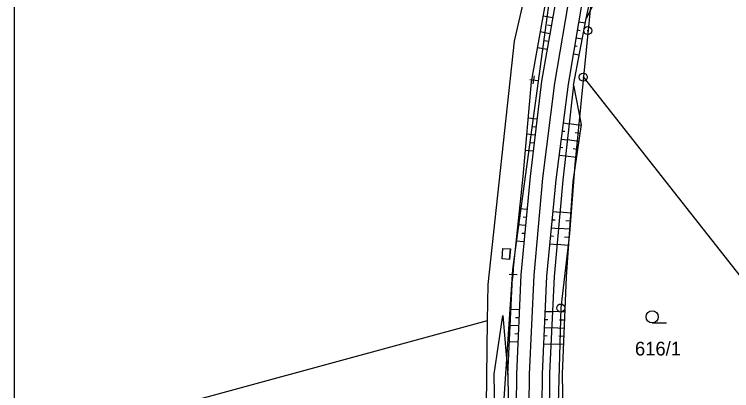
# Model space of a CAD drawing. Extents: x -558358 to -557517, y -1073786 to -1073189.
# Drawn here: x -558357.5 to -558268.9, y -1073715.2 to -1073668.8 of the extents above; entities that cross this region are included whole.
import ezdxf

# ---------------------------------------------------------------- set-up
doc = ezdxf.new("R2010")
doc.units = 0
for name, color, linetype in [('Body', 7, 'Continuous'), ('Hranice parcel', 7, 'Continuous'), ('Kolej', 7, 'Continuous'), ('Lomové body_krizky', 7, 'Continuous'), ('Návěst místo trati', 7, 'Continuous'), ('Parcelní čísla', 7, 'Continuous'), ('Přejezd - štěrkové lože', 7, 'Continuous'), ('Sonda - šrafa - vrstevnice', 7, 'Continuous'), ('Svazek obcí údolí Desné', 7, 'Continuous'), ('Vrstva 1', 7, 'Continuous'), ('Značky kultur', 7, 'Continuous'), ('ŽKN drážní hranice', 7, 'Continuous')]:
    doc.layers.add(name, color=color, linetype=linetype)

msp = doc.modelspace()

# ---------------------------------------------------------------- linework, layer by layer
at = {"layer": 'Body'}
for p, q in [((-558297.201, -1073697.684), (-558296.265, -1073697.749)), ((-558296.373, -1073699.041), (-558297.304, -1073698.971))]:
    msp.add_line(p, q, dxfattribs=at)
for points in [[(-558296.265, -1073697.749), (-558296.373, -1073699.041), (-558297.304, -1073698.971), (-558297.201, -1073697.684), (-558296.265, -1073697.749)], [(-558297.304, -1073698.971), (-558297.304, -1073698.971), (-558297.201, -1073697.684), (-558297.201, -1073697.684)], [(-558296.373, -1073699.041), (-558296.373, -1073699.041), (-558296.265, -1073697.749), (-558296.265, -1073697.749)]]:
    msp.add_lwpolyline(points, dxfattribs=at)
at = {"layer": 'Hranice parcel'}
for p, q in [((-558261.12, -1073709.7), (-558287.25, -1073676.53)), ((-558339.57, -1073717.56), (-558299.09, -1073706.57))]:
    msp.add_line(p, q, dxfattribs=at)
at = {"layer": 'Kolej'}
msp.add_lwpolyline([(-558287.365, -1073784.156), (-558289.56, -1073772.871), (-558290.655, -1073766.206), (-558291.244, -1073762.209), (-558292.77, -1073749.061), (-558293.618, -1073737.469), (-558294.023, -1073725.055), (-558293.93, -1073713.176), (-558293.343, -1073701.022), (-558292.273, -1073689.007), (-558290.767, -1073677.306), (-558288.802, -1073665.65), (-558286.315, -1073653.735), (-558283.342, -1073641.942), (-558279.999, -1073630.567), (-558276.235, -1073619.431), (-558271.867, -1073608.038), (-558267.229, -1073597.243), (-558261.985, -1073586.238), (-558256.491, -1073575.8), (-558250.409, -1073565.278), (-558246.055, -1073558.303)], dxfattribs=at)
at = {"layer": 'Lomové body_krizky'}
for points in [[(-558281.763, -1073647.437), (-558282.833, -1073654.479), (-558285.332, -1073666.203), (-558286.935, -1073669.338)], [(-558286.935, -1073669.338), (-558286.218, -1073666.1), (-558283.779, -1073654.254), (-558281.763, -1073647.437)], [(-558288.463, -1073677.538), (-558289.796, -1073689.277), (-558290.88, -1073701.164), (-558291.444, -1073713.13), (-558291.51, -1073724.978), (-558290.98, -1073737.221), (-558290.303, -1073748.774), (-558289.412, -1073757.852), (-558288.852, -1073759.4), (-558286.909, -1073759.37), (-558284.741, -1073757.826)], [(-558288.463, -1073677.538), (-558287.551, -1073682.415), (-558288.544, -1073689.423), (-558289.374, -1073701.199), (-558289.889, -1073713.191), (-558289.693, -1073724.945), (-558289.132, -1073737.15), (-558288.385, -1073748.554), (-558287.031, -1073757.61), (-558284.468, -1073754.179), (-558281.215, -1073749.294)], [(-558293.853, -1073762.99), (-558295.99, -1073758.489), (-558297.205, -1073749.273), (-558297.706, -1073737.714), (-558298.061, -1073725.185), (-558298.29, -1073713.182), (-558297.21, -1073705.961)], [(-558297.21, -1073705.961), (-558296.594, -1073713.219), (-558296.433, -1073725.029), (-558296.684, -1073737.611), (-558295.948, -1073749.108), (-558294.01, -1073759.601), (-558293.853, -1073762.99)]]:
    msp.add_lwpolyline(points, dxfattribs=at)
at = {"layer": 'Návěst místo trati'}
for p, q in [((-558293.863, -1073676.832), (-558292.873, -1073676.978)), ((-558293.441, -1073677.4), (-558293.295, -1073676.41)), ((-558296.441, -1073700.841), (-558295.443, -1073700.909)), ((-558295.976, -1073701.374), (-558295.908, -1073700.376))]:
    msp.add_line(p, q, dxfattribs=at)
at = {"layer": 'Přejezd - štěrkové lože'}
for p, q in [((-558291.044, -1073669.227), (-558292.223, -1073669.017)), ((-558288.463, -1073677.538), (-558286.935, -1073669.338)), ((-558287.812, -1073669.746), (-558287.036, -1073669.878)), ((-558291.22, -1073670.212), (-558291.691, -1073670.127)), ((-558287.978, -1073670.733), (-558287.675, -1073670.784)), ((-558291.396, -1073671.196), (-558292.575, -1073670.986)), ((-558291.571, -1073672.181), (-558292.043, -1073672.096)), ((-558288.145, -1073671.719), (-558287.402, -1073671.844)), ((-558291.747, -1073673.165), (-558292.926, -1073672.954)), ((-558288.312, -1073672.704), (-558288.021, -1073672.754)), ((-558288.479, -1073673.69), (-558287.768, -1073673.811)), ((-558292.999, -1073681.733), (-558294.065, -1073681.607)), ((-558289.723, -1073682.209), (-558289.004, -1073682.301)), ((-558293.117, -1073682.727), (-558293.531, -1073682.677)), ((-558293.235, -1073683.72), (-558294.24, -1073683.6)), ((-558289.85, -1073683.201), (-558289.557, -1073683.239)), ((-558293.353, -1073684.713), (-558293.742, -1073684.666)), ((-558289.977, -1073684.193), (-558289.23, -1073684.289)), ((-558293.471, -1073685.705), (-558294.414, -1073685.593)), ((-558290.104, -1073685.185), (-558289.8, -1073685.224)), ((-558290.231, -1073686.177), (-558289.455, -1073686.276)), ((-558294.222, -1073692.875), (-558295.121, -1073692.791)), ((-558290.997, -1073693.143), (-558290.156, -1073693.223)), ((-558294.315, -1073693.87), (-558294.68, -1073693.836)), ((-558291.093, -1073694.139), (-558290.754, -1073694.171)), ((-558294.409, -1073694.866), (-558295.334, -1073694.779)), ((-558291.188, -1073695.134), (-558290.338, -1073695.215)), ((-558294.502, -1073695.862), (-558294.877, -1073695.827)), ((-558291.284, -1073696.129), (-558290.942, -1073696.162)), ((-558294.595, -1073696.857), (-558295.547, -1073696.768)), ((-558291.38, -1073697.124), (-558290.519, -1073697.207)), ((-558295.161, -1073705.247), (-558296.215, -1073705.202)), ((-558291.951, -1073705.444), (-558291.084, -1073705.482)), ((-558295.204, -1073706.246), (-558295.627, -1073706.228)), ((-558291.995, -1073706.443), (-558291.649, -1073706.459)), ((-558295.247, -1073707.246), (-558296.31, -1073707.2)), ((-558292.038, -1073707.442), (-558291.178, -1073707.48)), ((-558295.29, -1073708.245), (-558295.717, -1073708.227)), ((-558292.082, -1073708.441), (-558291.739, -1073708.456)), ((-558295.332, -1073709.244), (-558296.404, -1073709.198)), ((-558292.125, -1073709.44), (-558291.272, -1073709.478))]:
    msp.add_line(p, q, dxfattribs=at)
for points in [[(-558236.565, -1073541.181), (-558242.627, -1073550.035), (-558251.802, -1073564.356), (-558258.077, -1073574.962), (-558263.679, -1073585.424), (-558268.893, -1073596.634), (-558273.555, -1073607.365), (-558277.841, -1073618.92), (-558281.554, -1073630.049), (-558284.863, -1073641.542), (-558287.933, -1073653.35), (-558290.359, -1073665.391), (-558292.442, -1073677.056), (-558293.843, -1073688.831), (-558294.976, -1073700.921), (-558295.502, -1073713.202), (-558295.648, -1073725.09), (-558295.338, -1073737.572), (-558294.508, -1073749.176), (-558292.854, -1073761.969)], [(-558289.764, -1073760.35), (-558291.17, -1073748.874), (-558292.009, -1073737.3), (-558292.422, -1073725.025), (-558292.288, -1073713.18), (-558291.762, -1073701.106), (-558290.619, -1073689.204), (-558289.112, -1073677.435), (-558287.165, -1073665.923), (-558284.764, -1073654.08), (-558281.791, -1073642.378), (-558278.307, -1073631.081), (-558274.714, -1073619.924), (-558270.318, -1073608.64), (-558265.699, -1073597.902), (-558260.505, -1073586.941), (-558255.049, -1073576.609), (-558248.928, -1073566.176), (-558239.895, -1073551.788), (-558235.828, -1073545.738)], [(-558296.594, -1073713.219), (-558296.03, -1073701.278), (-558294.695, -1073688.81), (-558293.676, -1073677.152), (-558291.537, -1073665.175), (-558289.198, -1073653.491), (-558286.075, -1073641.278), (-558282.618, -1073629.654), (-558278.766, -1073618.504)]]:
    msp.add_lwpolyline(points, dxfattribs=at)
at = {"layer": 'Sonda - šrafa - vrstevnice'}
for p, q in [((-558287.565, -1073682.516), (-558289.005, -1073682.312)), ((-558287.706, -1073683.507), (-558288.271, -1073683.426)), ((-558287.846, -1073684.497), (-558289.231, -1073684.3)), ((-558287.986, -1073685.487), (-558288.529, -1073685.41)), ((-558288.127, -1073686.477), (-558289.457, -1073686.289)), ((-558288.819, -1073693.325), (-558290.157, -1073693.231)), ((-558288.889, -1073694.322), (-558289.433, -1073694.284)), ((-558288.96, -1073695.32), (-558290.338, -1073695.223)), ((-558289.03, -1073696.317), (-558289.59, -1073696.278)), ((-558289.1, -1073697.315), (-558290.52, -1073697.215)), ((-558289.561, -1073705.546), (-558291.083, -1073705.481)), ((-558289.604, -1073706.545), (-558290.214, -1073706.519)), ((-558289.647, -1073707.544), (-558291.178, -1073707.479)), ((-558289.689, -1073708.544), (-558290.304, -1073708.517)), ((-558289.732, -1073709.542), (-558291.272, -1073709.476))]:
    msp.add_line(p, q, dxfattribs=at)
at = {"layer": 'Svazek obcí údolí Desné'}
for points in [[(-558237.23, -1073540.41), (-558250.35, -1073559.71), (-558264.4, -1073584.99), (-558277.08, -1073613.49), (-558283.33, -1073632.3), (-558290.3, -1073658.29), (-558296.01, -1073700.28), (-558297.13, -1073716.84), (-558297.21, -1073758.56)], [(-558299.09, -1073706.57), (-558299.03, -1073702.13), (-558295.75, -1073672.1), (-558286.79, -1073633.11)], [(-558281.64, -1073647.46), (-558284.84, -1073659.61), (-558286.44, -1073668.26), (-558287.25, -1073676.53)], [(-558287.25, -1073676.53), (-558288.33, -1073687.34), (-558288.98, -1073695.83), (-558290.03, -1073705.01), (-558290.44, -1073719.74), (-558289.69, -1073738.01), (-558289.37, -1073741.07)], [(-558298.08, -1073752.4), (-558299.44, -1073734.57), (-558299.09, -1073706.57)]]:
    msp.add_lwpolyline(points, dxfattribs=at)
at = {"layer": 'Vrstva 1'}
msp.add_line((-558357.534, -1073784.088), (-558357.534, -1073190.088), dxfattribs=at)
at = {"layer": 'Značky kultur'}
msp.add_line((-558278.753, -1073706.87), (-558277.003, -1073706.87), dxfattribs=at)
msp.add_circle((-558278.753, -1073706.12), 0.75, dxfattribs=at)
at = {"layer": 'ŽKN drážní hranice'}
for p, q in [((-558286.771, -1073670.816), (-558286.671, -1073670.816)), ((-558287.324, -1073676.558), (-558287.224, -1073676.558)), ((-558290.104, -1073705.037), (-558290.004, -1073705.037))]:
    msp.add_line(p, q, dxfattribs=at)
for centre in [(-558286.721, -1073670.816), (-558287.274, -1073676.558), (-558290.054, -1073705.037)]:
    msp.add_circle(centre, 0.499, dxfattribs=at)

# ---------------------------------------------------------------- texts
at = {"layer": 'Parcelní čísla'}
msp.add_text('616/1', height=1.7, dxfattribs=at).set_placement((-558280.89, -1073710.89))

doc.saveas('drawing.dxf')
